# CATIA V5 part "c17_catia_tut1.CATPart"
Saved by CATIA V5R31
Part number: Part1
Bounding box of the stored display mesh (mm): x 0 to 100, y -49.812 to 49.812, z 0 to 49.812
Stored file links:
  D:\PROJECTS\Project 2021\US EDITION\CATIA V5 6R 2021\Resources\Tutorial Files\c17_catia_v5_6r2021_tut\c17_catia_tut1.CATPart
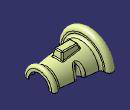
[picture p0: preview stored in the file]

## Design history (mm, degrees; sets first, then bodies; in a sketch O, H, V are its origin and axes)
Body1 (main body)
  Sketch1 on xy-plane, origin (0, 0, 0), H (1, 0, 0), V (0, 1, 0)
    point P1 (0, 30)
    line L1 (0, 30) -> (0, 42.5)
    arc A1 centre (7.5, 42.5) radius 7.5 from (0, 42.5) to (15, 42.5) cw
    point P3 (7.5, 42.5)
    line L2 (15, 42.5) -> (15, 35)
    point P5 (15, 35)
    line L3 (15, 35) -> (90.101, 24)
    point P6 (90.101, 24)
    arc A2 centre (95, 25) radius 5 from (90.101, 24) to (100, 25) cw
    point P7 (95, 25)
    line L4 (100, 25) -> (100, 20)
    point P9 (100, 20)
    axis line L5 (0, 0) -> (130.0291, 0)
    radius A1 = 7.5
    distance L1 L4 = 100
    radius A2 = 5
    radius about axis P1 L5 = 30
    radius about axis P3 L5 = 42.5
    radius about axis P5 L5 = 35
    radius about axis P9 L5 = 20
    radius about axis P7 L5 = 25
    radius about axis P6 L5 = 24
    coincidence: P1 V
    tangency: A1 L1, L2 A1, L4 A2
    vertical: L1 V, L2 V, L4 V
    horizontal: L5 H
  Revol1: Element1 Sketch1, Angle1 180
  Sketch2 on xy-plane, origin (0, 0, 0), H (1, 0, 0), V (0, 1, 0)
    point P1 (50, 29.8736)
    ellipse A1 centre (50, 29.8736) semi-axes 10, 5 rotation 90
    reference projected line E1 (90.101, 24) -> (15, 35) from Sketch1.L3
    reference projected point E2 (100, 20) from Sketch1.P9
    ellipse A2 centre (50, -29.8736) semi-axes 10, 5 rotation 270
    "Radius" A1 = 10
    "Radius" A1 = 5
    distance P1 E2 H = 50
    vertical: A1 V
    coincidence: P1 E1
    symmetry: A1 A2 H
  Extrude1: Element1 Sketch2, Lim1 40, Lim2 0, Direction xy-plane
  Trim1: Trimmed (Revol1; Extrude1)
  Fillet1: radius 5, on edge [face of Revol1 from Sketch1.L3 | face of Extrude1 from Sketch2.A2]; edge [face of Revol1 from Sketch1.L3 | face of Extrude1 from Sketch2.A1]
  Plane1: type Offset, RefPlane xy-plane, Offset 40
  Sketch3 on Plane1, origin (0, 0, 40), H (1, 0, 0), V (0, 1, 0)
    line L1 (30, 10) -> (65, 10)
    line L2 (65, 10) -> (65, -10)
    line L3 (65, -10) -> (30, -10)
    line L4 (30, -10) -> (30, 10)
    reference projected line E1 (100, 25) -> (100, -25) from edge [face of Revol1 from Sketch1.L4 | face of Revol1 from Sketch1.A2]
    distance L2 E1 = 35
    length L1 = 35
    length L2 = 20
    horizontal: L1 H, L3 H
    vertical: L2 V, L4 V
    symmetry: L1 L3 H
  Project1: ToProject Sketch3, Support Fillet1, Direction xy-plane
  Sketch4 on Plane1, origin (0, 0, 40), H (1, 0, 0), V (0, 1, 0)
    line L1 (32.5, 7.5) -> (62.5, 7.5)
    line L2 (62.5, 7.5) -> (62.5, -7.5)
    line L3 (62.5, -7.5) -> (32.5, -7.5)
    line L4 (32.5, -7.5) -> (32.5, 7.5)
    reference projected line E1 (100, 25) -> (100, -25) from edge [face of Revol1 from Sketch1.L4 | face of Revol1 from Sketch1.A2]
    distance L2 E1 = 37.5
    length L1 = 30
    length L2 = 15
    horizontal: L1 H, L3 H
    vertical: L2 V, L4 V
    symmetry: L3 L1 H
  Loft1: Sections (Project1; Sketch4), SectionCouplingPoints ({coupling CouplingPoints (vertex [face of Project1 | face of Project1]; vertex [element of Sketch4 | element of Sketch4])}; {coupling CouplingPoints (vertex [face of Project1 | face of Project1]; vertex [element of Sketch4 | element of Sketch4])}; {coupling CouplingPoints (vertex [face of Project1 | face of Project1]; vertex [element of Sketch4 | element of Sketch4])})
  Trim2: Trimmed (Loft1; Fillet1)
  Fill1: Boundary (edge of Loft1; edge of Loft1; edge of Loft1; edge of Loft1)
  Join1: Elements (Trim2; Fill1)
  Fillet2: radius 5, on edge [face of Revol1 from Sketch1.L3 | face of Revol1 from Sketch1.L2]; edge [face of Revol1 from Sketch1.A2 | face of Revol1 from Sketch1.L3]
  Fillet3: radius 2, on face of Fill1; edge [face of Loft1 | face of Loft1]; face of Loft1 (x4)
  Set1
    ThickSurface1: BotOffset 0, Surface Fillet3, TopOffset 1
